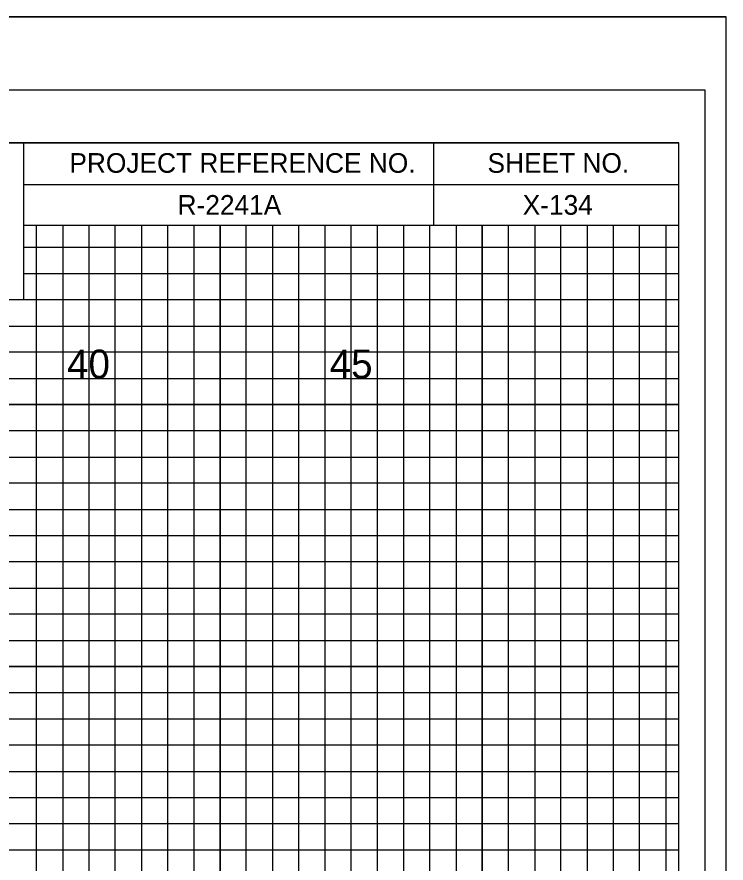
# Model space of a CAD drawing. Extents: x -4 to 103, y -2 to 280.
# Drawn here: x 89.87 to 103.4, y 192.9 to 209.05 of the extents above; entities that cross this region are included whole.
import ezdxf

# ---------------------------------------------------------------- set-up
doc = ezdxf.new("R2010")
doc.units = 0
for name, color, linetype in [('Exist XS Center Line Elevation Label', 7, 'Continuous'), ('Old_Level_63', 7, 'Continuous'), ('Prop XS Dump Level', 7, 'Continuous'), ('Prop XS Pvmt Edge Slope', 7, 'Continuous'), ('Prop XS SE Text', 7, 'Continuous'), ('Prop XS Side Slope Text', 7, 'Continuous'), ('Prop XS SS Elevation Text', 7, 'Continuous'), ('Sheet Cutting Line CELL', 7, 'Continuous'), ('Sheet Plot Border Inside CELL', 7, 'Continuous'), ('Sheet Plot Border Outside CELL', 7, 'Continuous')]:
    doc.layers.add(name, color=color, linetype=linetype)

msp = doc.modelspace()

# ---------------------------------------------------------------- linework, layer by layer
at = {"layer": 'Exist XS Center Line Elevation Label'}
for points in [[(91.25, 141.65), (91.25, 205.075), (93.75, 205.075), (93.75, 141.65)], [(96.25, 141.65), (96.25, 205.075), (98.75, 205.075), (98.75, 141.65)], [(101.25, 141.65), (101.25, 205.075)], [(90, 204.15), (102.5, 204.15)], [(0, 199.15), (102.5, 199.15), (102.5, 201.65), (0, 201.65)], [(0, 194.15), (102.5, 194.15), (102.5, 196.65), (0, 196.65)]]:
    msp.add_lwpolyline(points, dxfattribs=at)
at = {"layer": 'Old_Level_63'}
for p, q in [((90, 206.65), (102.5, 206.65)), ((90, 206.65), (102.5, 206.65)), ((97.825, 205.075), (97.825, 206.65)), ((101.875, 206.65), (101.875, 206.65)), ((102.5, 206.65), (102.5, 206.65)), ((102.5, 205.075), (102.5, 206.65)), ((102.5, 206.65), (102.5, 206.65)), ((102.5, 206.65), (102.5, 206.65)), ((102.5, 205.075), (102.5, 206.65)), ((90, 205.85), (102.5, 205.85)), ((90, 205.075), (102.5, 205.075)), ((99.4, 205.075), (99.4, 205.075)), ((99.4, 205.075), (99.4, 205.075))]:
    msp.add_line(p, q, dxfattribs=at)
for points in [[(102.5, 206.65), (0, 206.65), (0, 141.65), (102.5, 141.65)], [(83.75, 206.65), (90, 206.65), (90, 203.65), (83.75, 203.65)]]:
    msp.add_lwpolyline(points, close=True, dxfattribs=at)
at = {"layer": 'Prop XS Dump Level'}
for p, q in [((91.25, 141.65), (91.25, 205.075)), ((93.75, 141.65), (93.75, 205.075)), ((96.25, 141.65), (96.25, 205.075)), ((98.75, 141.65), (98.75, 205.075)), ((101.25, 141.65), (101.25, 205.075)), ((90, 204.15), (102.5, 204.15)), ((0, 201.65), (102.5, 201.65)), ((0, 199.15), (102.5, 199.15)), ((0, 196.65), (102.5, 196.65)), ((0, 194.15), (102.5, 194.15))]:
    msp.add_line(p, q, dxfattribs=at)
at = {"layer": 'Prop XS SE Text'}
for points in [[(90.25, 141.65), (90.25, 205.075), (90.75, 205.075), (90.75, 141.65)], [(91.75, 141.65), (91.75, 205.075), (92.25, 205.075), (92.25, 141.65)], [(92.75, 141.65), (92.75, 205.075), (93.25, 205.075), (93.25, 141.65)], [(94.25, 141.65), (94.25, 205.075), (94.75, 205.075), (94.75, 141.65)], [(95.25, 141.65), (95.25, 205.075), (95.75, 205.075), (95.75, 141.65)], [(96.75, 141.65), (96.75, 205.075), (97.25, 205.075), (97.25, 141.65)], [(97.75, 141.65), (97.75, 205.075), (98.25, 205.075), (98.25, 141.65)], [(99.25, 141.65), (99.25, 205.075), (99.75, 205.075), (99.75, 141.65)], [(100.25, 141.65), (100.25, 205.075)], [(100.25, 205.075), (100.75, 205.075), (100.75, 141.65), (101.75, 141.65), (101.75, 205.075), (102.25, 205.075), (102.25, 141.65)], [(102.5, 203.65), (102.5, 204.65), (90, 204.65)], [(0, 203.15), (102.5, 203.15), (102.5, 203.65), (0, 203.65)], [(0, 202.15), (102.5, 202.15), (102.5, 202.65), (0, 202.65)], [(0, 200.65), (102.5, 200.65), (102.5, 201.15), (0, 201.15)], [(0, 199.65), (102.5, 199.65), (102.5, 200.15), (0, 200.15)], [(0, 198.15), (102.5, 198.15), (102.5, 198.65), (0, 198.65)], [(0, 197.15), (102.5, 197.15), (102.5, 197.65), (0, 197.65)], [(0, 195.65), (102.5, 195.65), (102.5, 196.15), (0, 196.15)], [(0, 194.65), (102.5, 194.65), (102.5, 195.15), (0, 195.15)], [(0, 193.15), (102.5, 193.15), (102.5, 193.65), (0, 193.65)]]:
    msp.add_lwpolyline(points, dxfattribs=at)
at = {"layer": 'Sheet Cutting Line CELL'}
msp.add_line((-3.5, 209.05), (103.4, 209.05), dxfattribs=at)
at = {"layer": 'Sheet Plot Border Inside CELL'}
msp.add_lwpolyline([(103, 207.65), (-2.8, 207.65), (-2.8, 140.65), (103, 140.65)], close=True, dxfattribs=at)
at = {"layer": 'Sheet Plot Border Outside CELL'}
msp.add_lwpolyline([(103.4, 209.05), (-3.5, 209.05), (-3.5, 139.225), (103.4, 139.225)], close=True, dxfattribs=at)

# ---------------------------------------------------------------- texts
at = {"layer": 'Old_Level_63'}
for s, p in [('PROJECT REFERENCE NO.', (90.875, 206.075)), ('SHEET NO.', (98.85, 206.075))]:
    msp.add_text(s, height=0.375, dxfattribs=at).set_placement(p)
at = {"layer": 'Prop XS Pvmt Edge Slope'}
for s, p in [('40', (90.831, 202.15)), ('45', (95.84, 202.15))]:
    msp.add_text(s, height=0.55, dxfattribs=at).set_placement(p)
at = {"layer": 'Prop XS Side Slope Text'}
msp.add_text('X-134', height=0.375, dxfattribs=at).set_placement((99.521, 205.275))
at = {"layer": 'Prop XS SS Elevation Text'}
msp.add_text('R-2241A', height=0.375, dxfattribs=at).set_placement((92.938, 205.275))

doc.saveas('drawing.dxf')
